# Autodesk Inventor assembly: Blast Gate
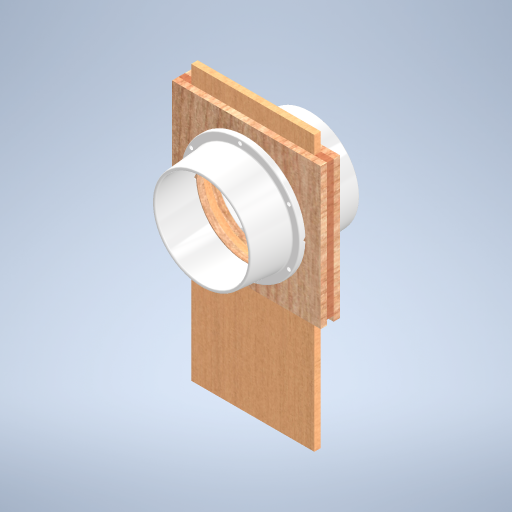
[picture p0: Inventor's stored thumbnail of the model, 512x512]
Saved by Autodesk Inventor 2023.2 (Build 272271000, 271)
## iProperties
Created: 2022-05
Part Number: Blast Gate
Document SubType Name: Assembly
Designer: elimb
Author: elimb
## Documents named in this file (5)
- C:\Users\elimb\Documents\Inventor Files\Blast Gate\Blast Gate.iam
- C:\Users\elimb\Documents\Inventor Files\Blast Gate\Connection.ipt
- C:\Users\elimb\Documents\Inventor Files\Blast Gate\Side.ipt
- C:\Users\elimb\Documents\Inventor Files\Blast Gate\Spacer.ipt
- C:\Users\elimb\Documents\Inventor Files\Blast Gate\Gate.ipt
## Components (7 placed, 4 different names)
1. Connection:1 — Mate:1, Mate:2, Mate:3, Mate:5
2. Side:1 — Mate:1, Mate:4, Angle:1, Angle:2, Mate:10, Angle:3
3. Spacer:1 — Mate:7, Flush:1, Flush:2
4. Spacer:2 — Mate:8, Flush:3, Flush:4, Mate:10
5. Side:2 — Mate:5, Mate:6, Angle:1, Mate:7, Mate:8, Flush:1, Flush:2, Flush:3, Flush:4, Mate:9
6. Connection:2 — Mate:3, Mate:4, Mate:6
7. Gate:1 — Mate:2, Mate:9, Angle:3
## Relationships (17: Mate 10, Flush 4, Angle 3)
- Mate:1: Connection:1 ↔ Side:1
- Mate:2: Connection:1 ↔ Gate:1
- Mate:3: Connection:1 ↔ Connection:2
- Mate:4: Side:1 ↔ Connection:2
- Mate:5: Connection:1 ↔ Side:2
- Mate:6: Side:2 ↔ Connection:2
- Angle:1: Side:1 ↔ Side:2
- Angle:2: Side:1
- Mate:7: Spacer:1 ↔ Side:2
- Mate:8: Spacer:2 ↔ Side:2
- Flush:1: Spacer:1 ↔ Side:2
- Flush:2: Spacer:1 ↔ Side:2
- Flush:3: Spacer:2 ↔ Side:2
- Flush:4: Spacer:2 ↔ Side:2
- Mate:9: Side:2 ↔ Gate:1
- Mate:10: Side:1 ↔ Spacer:2
- Angle:3: Side:1 ↔ Gate:1
